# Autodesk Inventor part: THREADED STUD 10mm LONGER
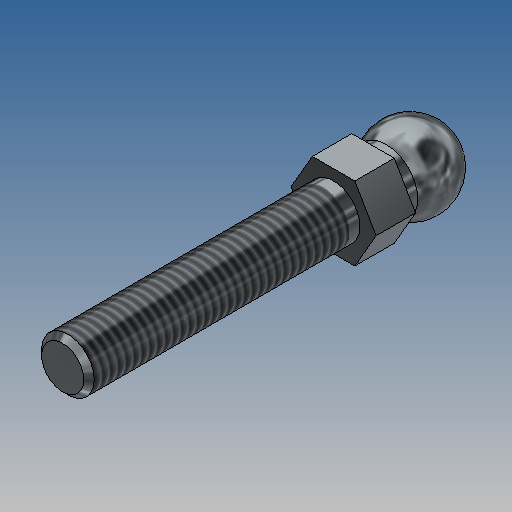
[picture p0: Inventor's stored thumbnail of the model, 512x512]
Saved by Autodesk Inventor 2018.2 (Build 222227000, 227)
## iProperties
Created: 2007-03
Part Number: THREADED STUD 10mm LONGER
Document SubType Name: Modeling
Designer: Andy Moles
Material: Steel
Mass: 52.5811 g
Surface Area: 26.5957 cm^2
Volume: 6.69823 cm^3
Density: 7.85 g/cm^3
Appearance: Zinc
Author: Andy Moles
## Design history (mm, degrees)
sketch "Sketch1"
  geometry: L1 (0, -7.5)-(0, 7.5); A1 r 7.5 centre (0, 0) between (0, -7.5) and (0, 7.5); 1 further point
  constraints: 2 end point, 2 point on circle, 1 centre point, 1 coincident, 1 midpoint, 1 vertical
  dimensions: "d5" = 15 distance of L1.start L1.end
revolve "Revolution1" sketch "Sketch1" stored, may be unused: angle "d1" = 90 deg
sketch "Sketch2"
  geometry: C1 r 6 at (0, 0); 1 further point
  constraints: 1 centre point, 1 coincident
  dimensions: "d2" = 12 diameter of C1
extrude "Extrusion1" join sketch "Sketch2" distance "d3" = 7; taper "d4" = 0 deg
sketch "Sketch3"
  geometry: L1 (-4.041, 7)-(4.041, 7); L2 (4.041, 7)-(8.083, 0); L3 (8.083, 0)-(4.041, -7); L4 (4.041, -7)-(-4.041, -7); L5 (-4.041, -7)-(-8.083, 0); L6 (-8.083, 0)-(-4.041, 7); C1 r 6 at (0, 0) reference; 1 further point
  constraints: 12 end point, 5 equal length, 1 horizontal, 1 horizontal alignment, 1 midpoint, 1 parallel, 1 vertical alignment
  dimensions: "d6" = 120 deg angle of L6 L5; "d7" = 120 deg angle of L1 L6; "d8" = 14 distance between parallel lines of L4 L1
extrude "Extrusion2" join sketch "Sketch3" distance "d9" = 7.5; taper "d10" = 0 deg
sketch "Sketch4"
  geometry: C1 r 5 at (0, 0); 1 further point
  constraints: 1 centre point, 1 coincident
  dimensions: "d11" = 10 diameter of C1
extrude "Extrusion3" join sketch "Sketch4" distance "d12" = 51.5; taper "d13" = 0 deg
thread "Thread1" dims "d14" = 49.5, "d15" = 2
chamfer "Chamfer1" distance "d16" = 1; stored, may be unused: second distance "d17" = 2, angle "d18" = 45 deg
body "Solid1"
